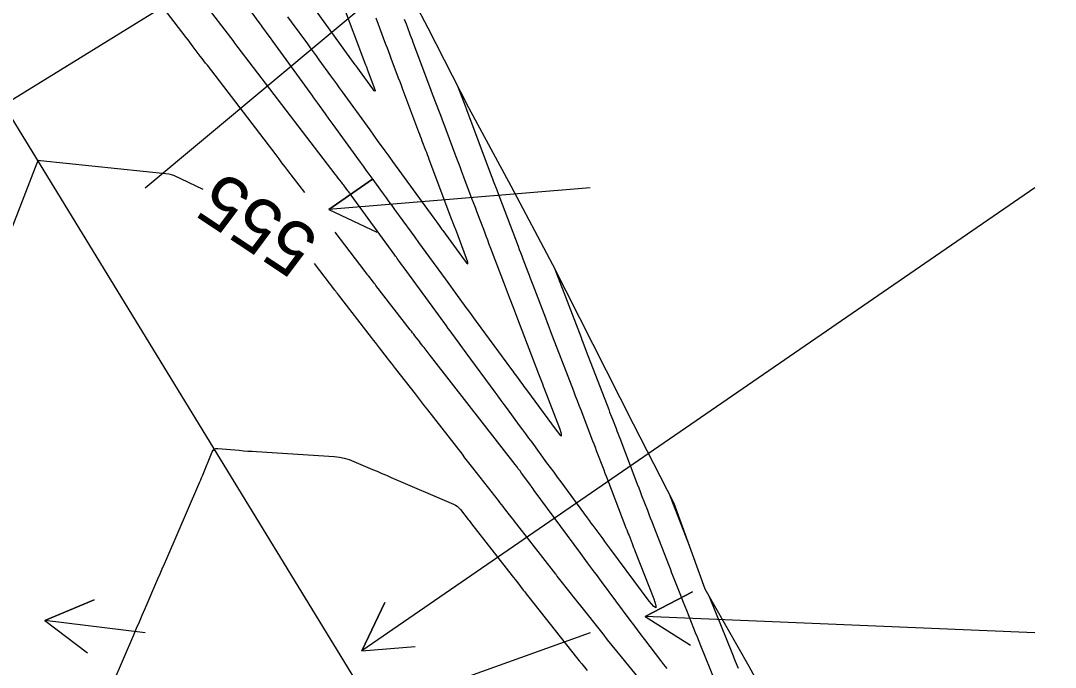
# Model space of a CAD drawing. Extents: x 954385 to 988206, y 1868364 to 1924553.
# Drawn here: x 957043.1 to 957159.4, y 1921015.1 to 1921087.7 of the extents above; entities that cross this region are included whole.
import ezdxf

# ---------------------------------------------------------------- set-up
doc = ezdxf.new("R2010")
doc.units = 0
for name, color, linetype in [('24', 7, 'Continuous'), ('26', 7, 'Continuous'), ('5', 7, 'Continuous'), ('6', 7, 'Continuous'), ('7', 7, 'Continuous'), ('Default', 7, 'Continuous')]:
    doc.layers.add(name, color=color, linetype=linetype)

msp = doc.modelspace()

# ---------------------------------------------------------------- linework, layer by layer
at = {"layer": '24'}
msp.add_lwpolyline([(957084.26, 1921095.8), (957088.9, 1921086.91), (957093.47, 1921077.98), (957098.24, 1921069.18), (957102.92, 1921060.32), (957107.46, 1921051.38), (957111.99, 1921042.42), (957116.56, 1921033.5), (957120.03, 1921023.9), (957124.96, 1921015.19), (957129.77, 1921006.41), (957135.24, 1920998.03), (957142.23, 1920990.59), (957147.77, 1920982.25), (957156.36, 1920975.79), (957167.75, 1920971.03)], dxfattribs=at)
at = {"layer": '26'}
for points in [[(957107.13, 1921118.93), (957024.32, 1921067.81), (957027.16, 1921073.09), (957024.32, 1921067.81), (957030.32, 1921067.99)], [(957057.13, 1921068.93), (957098.27, 1921103.28), (957096.2, 1921097.65), (957098.27, 1921103.28), (957092.36, 1921102.25)], [(957107.13, 1921068.93), (957077.76, 1921066.52), (957082.69, 1921069.93), (957077.76, 1921066.52), (957083.18, 1921063.95)], [(957157.13, 1921068.93), (957081.5, 1921016.92), (957084.08, 1921022.34), (957081.5, 1921016.92), (957087.48, 1921017.39)], [(957157.13, 1921018.93), (957113.34, 1921020.77), (957118.66, 1921023.55), (957113.34, 1921020.77), (957118.41, 1921017.55)], [(957057.13, 1921018.93), (957045.87, 1921020.31), (957051.39, 1921022.66), (957045.87, 1921020.31), (957050.66, 1921016.7)], [(957107.13, 1921018.93), (957054.45, 1921000.01), (957058.33, 1921004.59), (957054.45, 1921000.01), (957060.35, 1920998.94)]]:
    msp.add_lwpolyline(points, dxfattribs=at)
at = {"layer": '6'}
for points in [[(957079.17, 1921090.03), (957081.91, 1921082.77), (957081.99, 1921082.55), (957082.13, 1921082.16), (957082.15, 1921082.11), (957082.88, 1921080.17), (957082.97, 1921079.9), (957082.97, 1921079.8), (957082.88, 1921079.86), (957082.71, 1921080.07), (957081.22, 1921082.13), (957080.84, 1921082.66), (957080.75, 1921082.78), (957075.61, 1921089.87)], [(957063.66, 1921068.76), (957060.36, 1921070.32), (957060.22, 1921070.38), (957060.08, 1921070.42), (957059.94, 1921070.46), (957059.79, 1921070.48), (957045.36, 1921071.97), (957045.34, 1921071.97), (957045.32, 1921071.97), (957045.31, 1921071.97), (957045.29, 1921071.98), (957045.1, 1921072), (957045.09, 1921072), (957045.07, 1921071.99), (957045.07, 1921071.99), (957045.06, 1921071.97), (957044.99, 1921071.79), (957044.99, 1921071.78), (957044.98, 1921071.76), (957044.98, 1921071.75), (957044.97, 1921071.73), (957034.36, 1921044.36)], [(957115.8, 1921009.94), (957110.66, 1921016.24), (957110.14, 1921016.88), (957109.62, 1921017.53), (957109.1, 1921018.17), (957108.59, 1921018.82), (957105.94, 1921022.16), (957105.72, 1921022.44), (957105.5, 1921022.72), (957105.28, 1921023), (957105.06, 1921023.28), (957103.45, 1921025.3), (957103.41, 1921025.36), (957103.36, 1921025.42), (957103.31, 1921025.48), (957103.27, 1921025.54), (957098.9, 1921031.15), (957098.72, 1921031.37), (957098.55, 1921031.59), (957098.38, 1921031.81), (957098.21, 1921032.03), (957097.52, 1921032.92), (957097.35, 1921033.14), (957097.17, 1921033.36), (957097, 1921033.58), (957096.83, 1921033.8), (957093.97, 1921037.47), (957093.67, 1921037.85), (957093.37, 1921038.24), (957093.07, 1921038.62), (957092.78, 1921039), (957088.89, 1921043.99), (957088.54, 1921044.44), (957088.19, 1921044.88), (957087.85, 1921045.33), (957087.5, 1921045.78), (957085.25, 1921048.66), (957085.03, 1921048.95), (957084.8, 1921049.24), (957084.58, 1921049.52), (957084.36, 1921049.81), (957083.46, 1921050.97), (957083.24, 1921051.26), (957083.02, 1921051.55), (957082.79, 1921051.84), (957082.57, 1921052.12), (957078.86, 1921056.93), (957078.76, 1921057.06), (957078.65, 1921057.2), (957078.55, 1921057.33), (957078.45, 1921057.46), (957076.16, 1921060.46)], [(957116.01, 1921034.57), (957116.39, 1921033.59), (957116.44, 1921033.46), (957116.45, 1921033.43), (957116.46, 1921033.39), (957118.28, 1921028.75)], [(957120.52, 1921023.03), (957123.13, 1921016.54), (957123.21, 1921016.34), (957123.29, 1921016.14), (957123.37, 1921015.94), (957123.45, 1921015.75), (957123.77, 1921014.95)]]:
    msp.add_lwpolyline(points, dxfattribs=at)
at = {"layer": '7'}
for points in [[(957064.81, 1921094.62), (957069.92, 1921087.53), (957070.05, 1921087.35), (957070.17, 1921087.18), (957070.3, 1921087), (957070.42, 1921086.83), (957070.93, 1921086.13), (957071.18, 1921085.79), (957071.43, 1921085.44), (957075.63, 1921079.65), (957075.85, 1921079.36), (957076.06, 1921079.06), (957076.28, 1921078.76), (957076.49, 1921078.46), (957077.36, 1921077.27), (957077.79, 1921076.67), (957078.22, 1921076.08), (957081.31, 1921071.82), (957081.63, 1921071.38), (957081.95, 1921070.94), (957082.27, 1921070.49), (957082.59, 1921070.05), (957083.88, 1921068.28), (957084.2, 1921067.84), (957084.52, 1921067.39), (957084.84, 1921066.95), (957085.16, 1921066.51), (957087.01, 1921063.96), (957087.43, 1921063.39), (957087.84, 1921062.82), (957088.26, 1921062.25), (957088.67, 1921061.68), (957090.84, 1921058.71), (957091.13, 1921058.31), (957091.43, 1921057.91), (957091.72, 1921057.51), (957092.01, 1921057.11), (957093.17, 1921055.51), (957093.47, 1921055.11), (957093.76, 1921054.71), (957094.05, 1921054.32), (957094.34, 1921053.92), (957098.3, 1921048.54), (957098.44, 1921048.35), (957098.58, 1921048.16), (957098.72, 1921047.97), (957098.86, 1921047.77), (957099.42, 1921047.01), (957099.56, 1921046.82), (957099.7, 1921046.63), (957099.84, 1921046.44), (957099.98, 1921046.25), (957103.33, 1921041.7), (957103.73, 1921041.2), (957103.92, 1921041.07), (957103.92, 1921041.31), (957103.72, 1921041.91), (957102.02, 1921046.35), (957101.91, 1921046.63), (957101.81, 1921046.9), (957101.39, 1921048), (957099.01, 1921054.19), (957098.9, 1921054.49), (957098.78, 1921054.79), (957098.66, 1921055.1), (957098.55, 1921055.4), (957098.08, 1921056.61), (957097.97, 1921056.92), (957097.85, 1921057.22), (957097.74, 1921057.52), (957097.62, 1921057.83), (957095.99, 1921062.13), (957095.81, 1921062.59), (957095.64, 1921063.05), (957095.46, 1921063.51), (957095.29, 1921063.97), (957094.59, 1921065.81), (957094.41, 1921066.27), (957094.24, 1921066.73), (957094.06, 1921067.19), (957093.89, 1921067.65), (957092.95, 1921070.16), (957092.73, 1921070.73), (957092.52, 1921071.3), (957092.3, 1921071.87), (957092.09, 1921072.44), (957090.96, 1921075.45), (957090.8, 1921075.86), (957090.65, 1921076.26), (957090.5, 1921076.66), (957090.35, 1921077.07), (957089.74, 1921078.68), (957089.59, 1921079.08), (957089.44, 1921079.49), (957089.29, 1921079.89), (957089.13, 1921080.29), (957087.26, 1921085.28), (957087.16, 1921085.53), (957087.07, 1921085.79), (957086.97, 1921086.05), (957086.87, 1921086.3), (957086.49, 1921087.33), (957086.39, 1921087.59), (957086.29, 1921087.85)], [(957075.07, 1921068.42), (957073.18, 1921070.89), (957072.84, 1921071.33), (957072.51, 1921071.77), (957072.18, 1921072.2), (957071.84, 1921072.64), (957064.12, 1921082.72), (957063.93, 1921082.97), (957063.73, 1921083.23), (957063.53, 1921083.49), (957063.33, 1921083.75), (957062.54, 1921084.79), (957062.34, 1921085.05), (957062.15, 1921085.31), (957061.95, 1921085.57), (957061.75, 1921085.83), (957057.82, 1921091.01)], [(957092.28, 1921080.3), (957093.09, 1921078.16), (957093.2, 1921077.86), (957093.24, 1921077.75), (957096.02, 1921070.35), (957096.1, 1921070.15), (957096.18, 1921069.94), (957096.25, 1921069.74), (957096.33, 1921069.53), (957096.64, 1921068.71), (957096.72, 1921068.5), (957096.8, 1921068.3), (957096.87, 1921068.09), (957096.95, 1921067.89), (957099.04, 1921062.39), (957099.18, 1921062.03), (957099.31, 1921061.67), (957099.45, 1921061.31), (957099.59, 1921060.95), (957100.14, 1921059.51), (957100.27, 1921059.15), (957100.41, 1921058.79), (957100.55, 1921058.43), (957100.69, 1921058.06), (957102.11, 1921054.34), (957102.31, 1921053.83), (957102.5, 1921053.33), (957102.7, 1921052.82), (957102.89, 1921052.32), (957103.86, 1921049.79), (957104.44, 1921048.28), (957105.27, 1921046.12), (957105.47, 1921045.59), (957105.67, 1921045.06), (957105.88, 1921044.53), (957106.08, 1921044), (957107.41, 1921040.52), (957107.55, 1921040.16), (957107.69, 1921039.79), (957107.83, 1921039.43), (957107.97, 1921039.07), (957108.53, 1921037.62), (957108.67, 1921037.25), (957108.81, 1921036.89), (957108.94, 1921036.53), (957109.08, 1921036.17), (957111.16, 1921030.74), (957111.25, 1921030.52), (957111.33, 1921030.3), (957111.42, 1921030.08), (957111.51, 1921029.86), (957111.85, 1921028.97), (957111.94, 1921028.75), (957112.02, 1921028.53), (957112.11, 1921028.31), (957112.2, 1921028.09), (957114.28, 1921022.76), (957114.53, 1921022.02), (957114.53, 1921021.73), (957114.29, 1921021.89), (957113.79, 1921022.49), (957109.47, 1921028.29), (957109.25, 1921028.59), (957109.03, 1921028.89), (957108.81, 1921029.19), (957108.59, 1921029.49), (957107.71, 1921030.69), (957107.49, 1921030.99), (957107.27, 1921031.28), (957107.05, 1921031.58), (957106.83, 1921031.88), (957103.88, 1921035.9), (957103.48, 1921036.44), (957103.09, 1921036.98), (957102.69, 1921037.52), (957102.29, 1921038.06), (957100.61, 1921040.35), (957100.26, 1921040.82), (957099.91, 1921041.29), (957099.57, 1921041.76), (957099.22, 1921042.24), (957097.84, 1921044.12), (957097.49, 1921044.59), (957097.14, 1921045.06), (957096.8, 1921045.53), (957096.45, 1921046), (957093.21, 1921050.41), (957093.01, 1921050.68), (957092.81, 1921050.96), (957092.61, 1921051.23), (957092.41, 1921051.5), (957091.6, 1921052.6), (957091.4, 1921052.87), (957091.2, 1921053.15), (957091, 1921053.42), (957090.8, 1921053.7), (957086.12, 1921060.1), (957085.95, 1921060.33), (957085.78, 1921060.56), (957085.45, 1921061.02), (957085.37, 1921061.14), (957085.28, 1921061.25), (957085.2, 1921061.37), (957085.11, 1921061.48), (957080.29, 1921068.13), (957080.2, 1921068.26), (957080.11, 1921068.38), (957080.02, 1921068.5), (957079.92, 1921068.62), (957079.54, 1921069.13), (957079.45, 1921069.24), (957079.36, 1921069.36), (957079.28, 1921069.47), (957079.19, 1921069.58), (957078.84, 1921070.03), (957078.67, 1921070.26), (957078.5, 1921070.49), (957067.48, 1921084.88), (957067.36, 1921085.03), (957067.15, 1921085.31), (957067.13, 1921085.34), (957062.24, 1921091.77)], [(957073.14, 1921088.18), (957073.55, 1921087.61), (957075.36, 1921085.12), (957075.68, 1921084.67), (957076.01, 1921084.22), (957076.34, 1921083.77), (957076.66, 1921083.32), (957077.97, 1921081.52), (957078.29, 1921081.07), (957078.62, 1921080.62), (957078.95, 1921080.17), (957079.27, 1921079.72), (957082.37, 1921075.46), (957082.8, 1921074.87), (957083.22, 1921074.27), (957084.08, 1921073.09), (957084.51, 1921072.5), (957084.94, 1921071.91), (957089.57, 1921065.53), (957089.9, 1921065.07), (957090.23, 1921064.61), (957090.32, 1921064.5), (957090.4, 1921064.38), (957090.48, 1921064.27), (957090.57, 1921064.16), (957092.97, 1921060.86), (957093.26, 1921060.51), (957093.4, 1921060.41), (957093.4, 1921060.58), (957093.25, 1921061.02), (957092.03, 1921064.25), (957091.96, 1921064.43), (957091.89, 1921064.61), (957091.75, 1921064.98), (957091.71, 1921065.07), (957091.68, 1921065.17), (957091.64, 1921065.26), (957091.61, 1921065.35), (957089.05, 1921072.14), (957088.96, 1921072.4), (957088.86, 1921072.65), (957088.77, 1921072.91), (957088.67, 1921073.16), (957088.28, 1921074.18), (957088.19, 1921074.44), (957088.09, 1921074.7), (957088, 1921074.95), (957087.9, 1921075.21), (957086.09, 1921080.01), (957085.93, 1921080.43), (957085.78, 1921080.85), (957085.62, 1921081.27), (957085.46, 1921081.7), (957084.82, 1921083.38), (957084.66, 1921083.8), (957084.51, 1921084.22), (957084.35, 1921084.65), (957084.19, 1921085.07), (957083.08, 1921088)], [(957115.78, 1921014.92), (957115.43, 1921015.37), (957115.08, 1921015.83), (957113.3, 1921018.18), (957112.88, 1921018.73), (957112.47, 1921019.27), (957112.06, 1921019.82), (957111.65, 1921020.37), (957108.42, 1921024.7), (957108.23, 1921024.96), (957108.03, 1921025.23), (957107.84, 1921025.49), (957107.64, 1921025.75), (957106.86, 1921026.8), (957106.67, 1921027.06), (957106.47, 1921027.32), (957106.28, 1921027.59), (957106.08, 1921027.85), (957100.86, 1921034.95), (957100.73, 1921035.13), (957100.53, 1921035.41), (957100.46, 1921035.5), (957099.44, 1921036.89), (957099.26, 1921037.13), (957099.07, 1921037.38), (957098.89, 1921037.62), (957098.7, 1921037.86), (957089.58, 1921049.57), (957089.45, 1921049.74), (957089.31, 1921049.92), (957089.17, 1921050.09), (957089.04, 1921050.27), (957088.48, 1921050.99), (957088.35, 1921051.16), (957088.22, 1921051.32), (957088.09, 1921051.49), (957087.96, 1921051.66), (957087.44, 1921052.33), (957087.31, 1921052.5), (957087.18, 1921052.66), (957087.05, 1921052.83), (957086.92, 1921053), (957083.07, 1921057.98), (957082.97, 1921058.11), (957082.87, 1921058.24), (957082.77, 1921058.37), (957082.67, 1921058.5), (957082.27, 1921059.02), (957082.17, 1921059.15), (957082.06, 1921059.28), (957081.96, 1921059.41), (957081.86, 1921059.55), (957078.48, 1921063.97)], [(957103.18, 1921059.81), (957106.13, 1921052.12), (957106.22, 1921051.86), (957106.32, 1921051.61), (957106.71, 1921050.6), (957109.23, 1921044.02), (957109.33, 1921043.75), (957109.44, 1921043.49), (957109.54, 1921043.22), (957109.64, 1921042.96), (957110.05, 1921041.89), (957110.15, 1921041.63), (957110.25, 1921041.36), (957110.35, 1921041.09), (957110.46, 1921040.83), (957112.28, 1921036.07), (957112.44, 1921035.65), (957112.6, 1921035.23), (957112.76, 1921034.81), (957112.92, 1921034.39), (957113.57, 1921032.71), (957113.73, 1921032.28), (957113.89, 1921031.86), (957114.06, 1921031.44), (957114.22, 1921031.02), (957115.75, 1921027.1), (957115.94, 1921026.63), (957116.12, 1921026.16), (957116.3, 1921025.69), (957116.49, 1921025.22), (957117.22, 1921023.34), (957117.4, 1921022.87), (957117.59, 1921022.4), (957117.77, 1921021.93), (957117.96, 1921021.47), (957118.77, 1921019.47), (957118.96, 1921018.98), (957119.16, 1921018.49), (957119.36, 1921018), (957119.55, 1921017.51), (957121.15, 1921013.54)], [(957053.54, 1921013.33), (957055.85, 1921018.7), (957056.17, 1921019.45), (957056.49, 1921020.19), (957056.81, 1921020.93), (957057.13, 1921021.68), (957058.57, 1921024.99), (957058.82, 1921025.57), (957059.06, 1921026.14), (957059.31, 1921026.71), (957059.56, 1921027.28), (957063.18, 1921035.66), (957063.28, 1921035.9), (957063.38, 1921036.13), (957063.48, 1921036.37), (957063.58, 1921036.6), (957064.67, 1921039.27), (957064.77, 1921039.46), (957064.91, 1921039.58), (957065.08, 1921039.64), (957065.29, 1921039.65), (957067.71, 1921039.45), (957068.19, 1921039.41), (957068.67, 1921039.37), (957069.15, 1921039.34), (957069.63, 1921039.3), (957078.39, 1921038.74), (957078.96, 1921038.68), (957079.51, 1921038.57), (957080.06, 1921038.42), (957080.59, 1921038.21), (957082.69, 1921037.31), (957083.22, 1921037.09), (957083.74, 1921036.86), (957084.27, 1921036.64), (957084.79, 1921036.41), (957091.78, 1921033.41), (957092.01, 1921033.3), (957092.21, 1921033.16), (957092.4, 1921032.99), (957092.57, 1921032.8), (957093.45, 1921031.66), (957093.55, 1921031.55), (957093.73, 1921031.31), (957093.82, 1921031.19), (957098.38, 1921025.34), (957098.54, 1921025.14), (957098.7, 1921024.94), (957098.85, 1921024.74), (957099.01, 1921024.54), (957099.63, 1921023.73), (957099.79, 1921023.53), (957099.95, 1921023.33), (957100.11, 1921023.13), (957100.26, 1921022.93), (957105.62, 1921016.17), (957105.91, 1921015.81), (957106.21, 1921015.44), (957106.5, 1921015.07), (957106.8, 1921014.71)]]:
    msp.add_lwpolyline(points, dxfattribs=at)
at = {"layer": 'Default'}
msp.add_line((957221.14, 1920784.24), (956045.8, 1922705.18), dxfattribs=at)

# ---------------------------------------------------------------- texts
at = {"layer": '5'}
msp.add_text('555', height=6, rotation=146.4893, dxfattribs=at).set_placement((957076.94, 1921063.58))

doc.saveas('drawing.dxf')
